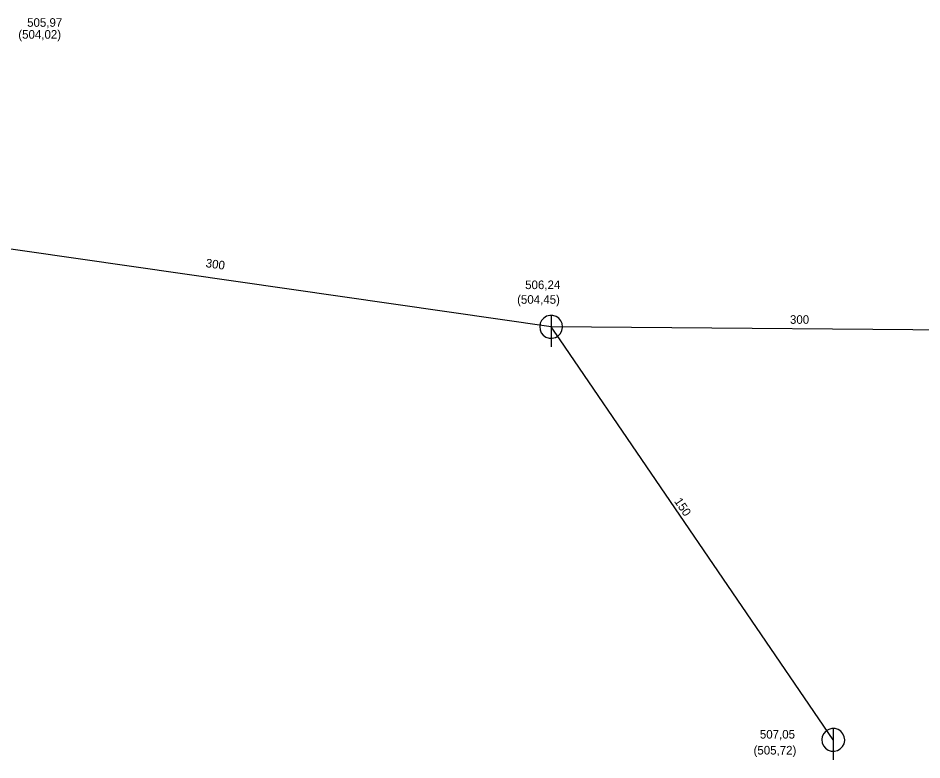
# Model space of a CAD drawing. Extents: x -476058 to -471893, y -1155786 to -1152000.
# Drawn here: x -475372.4 to -475293.5, y -1154316.5 to -1154251.7 of the extents above; entities that cross this region are included whole.
import ezdxf

# ---------------------------------------------------------------- set-up
doc = ezdxf.new("R2010")
doc.units = 0
for name, color, linetype in [('Vrstva 10', 7, 'Continuous'), ('Vrstva 18', 7, 'Continuous'), ('Vrstva 19', 7, 'Continuous'), ('Vrstva 3', 7, 'Continuous'), ('Vrstva 4', 7, 'Continuous'), ('Vrstva 45', 7, 'Continuous'), ('Vrstva 50', 7, 'Continuous')]:
    doc.layers.add(name, color=color, linetype=linetype)

msp = doc.modelspace()

# ---------------------------------------------------------------- linework, layer by layer
at = {"layer": 'Vrstva 10'}
for p, q in [((-475325.84, -1154277.68), (-475325.84, -1154280.428)), ((-475301.22, -1154313.74), (-475301.22, -1154316.488))]:
    msp.add_line(p, q, dxfattribs=at)
for points in [[(-475324.84, -1154278.68), (-475324.879, -1154278.401), (-475324.996, -1154278.144), (-475325.179, -1154277.929), (-475325.415, -1154277.775), (-475325.685, -1154277.692), (-475325.967, -1154277.688), (-475326.239, -1154277.763), (-475326.479, -1154277.911), (-475326.669, -1154278.12), (-475326.792, -1154278.374), (-475326.84, -1154278.652), (-475326.808, -1154278.933), (-475326.699, -1154279.193), (-475326.521, -1154279.412), (-475326.29, -1154279.574), (-475326.022, -1154279.664), (-475325.74, -1154279.676), (-475325.466, -1154279.608), (-475325.222, -1154279.467), (-475325.027, -1154279.263), (-475324.897, -1154279.013), (-475324.841, -1154278.736), (-475324.84, -1154278.68)], [(-475300.22, -1154314.74), (-475300.259, -1154314.461), (-475300.376, -1154314.204), (-475300.559, -1154313.989), (-475300.795, -1154313.835), (-475301.065, -1154313.752), (-475301.347, -1154313.748), (-475301.619, -1154313.823), (-475301.859, -1154313.971), (-475302.049, -1154314.18), (-475302.172, -1154314.434), (-475302.22, -1154314.712), (-475302.188, -1154314.993), (-475302.079, -1154315.253), (-475301.901, -1154315.472), (-475301.67, -1154315.634), (-475301.402, -1154315.724), (-475301.12, -1154315.736), (-475300.846, -1154315.668), (-475300.602, -1154315.527), (-475300.407, -1154315.323), (-475300.277, -1154315.073), (-475300.221, -1154314.796), (-475300.22, -1154314.74)]]:
    msp.add_lwpolyline(points, dxfattribs=at)
at = {"layer": 'Vrstva 45'}
for points in [[(-475325.84, -1154278.68), (-475376.26, -1154271.44)], [(-475283.757, -1154279.023), (-475325.84, -1154278.68)]]:
    msp.add_lwpolyline(points, dxfattribs=at)
at = {"layer": 'Vrstva 50'}
for points in [[(-475325.065, -1154279.815), (-475325.84, -1154278.68)], [(-475301.22, -1154314.74), (-475325.065, -1154279.815)]]:
    msp.add_lwpolyline(points, dxfattribs=at)

# ---------------------------------------------------------------- texts
at = {"layer": 'Vrstva 18'}
for rotation, p in [(351.82854, (-475356.025, -1154273.464)), (0.08882, (-475304.996, -1154278.419))]:
    msp.add_text('300 ', height=0.75, rotation=rotation, dxfattribs=at).set_placement(p)
at = {"layer": 'Vrstva 19'}
msp.add_text('150 ', height=0.75, rotation=304.32326, dxfattribs=at).set_placement((-475315.133, -1154293.917))
at = {"layer": 'Vrstva 3'}
for s, p in [('505,97', (-475371.572, -1154252.489)), ('506,24', (-475328.108, -1154275.387)), ('507,05', (-475307.622, -1154314.624))]:
    msp.add_text(s, height=0.75, dxfattribs=at).set_placement(p)
at = {"layer": 'Vrstva 4'}
for s, p in [('(504,02)', (-475372.343, -1154253.527)), ('(504,45)', (-475328.81, -1154276.668)), ('(505,72)', (-475308.175, -1154316.015))]:
    msp.add_text(s, height=0.75, dxfattribs=at).set_placement(p)

doc.saveas('drawing.dxf')
